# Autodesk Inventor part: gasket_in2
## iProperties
Created: 2007-12
Part Number: gasket_in2
Document SubType Name: Modeling
Designer: Arthur Queval
Author: Arthur Queval
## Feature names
1. Extrusion1
2. Fillet1
